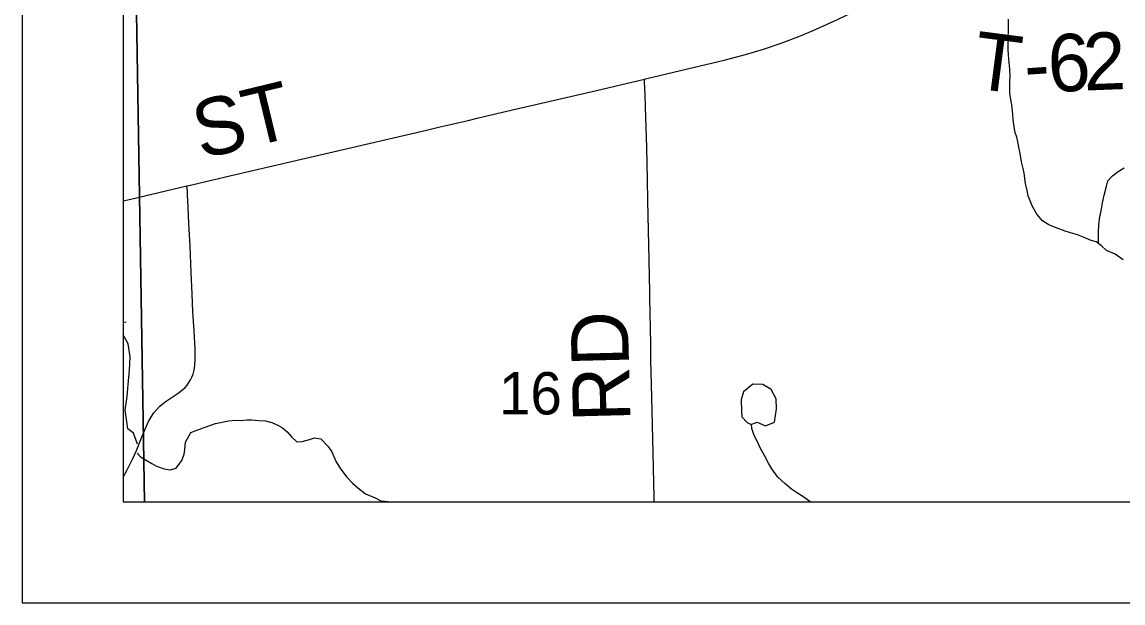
# Model space of a CAD drawing. Extents: x 0 to 34, y -5 to 22.
# Drawn here: x 2 to 3.09, y 14 to 14.575 of the extents above; entities that cross this region are included whole.
import ezdxf

# ---------------------------------------------------------------- set-up
doc = ezdxf.new("R2010")
doc.units = 0
for name, color, linetype in [('GM_X_City_Street', 7, 'Continuous'), ('GM_X_County_Road', 7, 'Continuous'), ('GM_X_County_Road_Text', 7, 'Continuous'), ('GM_X_Minor_Lake', 7, 'Continuous'), ('GM_X_Minor_River', 7, 'Continuous'), ('GM_X_Section_Text', 7, 'Continuous'), ('GM_X_Township_Road', 7, 'Continuous'), ('GM_X_Township_Road_Text', 7, 'Continuous'), ('GM_X_US_Route', 7, 'Continuous'), ('SH_Cut_Line', 7, 'Continuous'), ('SH_Data', 7, 'Continuous')]:
    doc.layers.add(name, color=color, linetype=linetype)

msp = doc.modelspace()

# ---------------------------------------------------------------- linework, layer by layer
at = {"layer": 'GM_X_City_Street'}
for points in [[(2.1212, 14.1), (3.1115, 14.1), (3.104, 14.6056), (2.1133, 14.5841)], [(2.1, 14.584), (2.1, 14.1), (2.1212, 14.1), (2.1133, 14.5841)]]:
    msp.add_lwpolyline(points, close=True, dxfattribs=at)
at = {"layer": 'GM_X_County_Road'}
msp.add_line((2.1, 14.2777), (2.103, 14.2784), dxfattribs=at)
for points in [[(2.6174, 14.5186), (2.6591, 14.5285), (2.6954, 14.5371), (2.7164, 14.5427), (2.7341, 14.5482), (2.7517, 14.5542), (2.7692, 14.5608), (2.7835, 14.5665), (2.8033, 14.5754), (2.82, 14.5835), (2.8336, 14.5909), (2.841, 14.5953)], [(2.1633, 14.4128), (2.168, 14.4139), (2.2072, 14.423), (2.2525, 14.4336), (2.2767, 14.4392), (2.3039, 14.4456), (2.4004, 14.4681), (2.4124, 14.4708), (2.4183, 14.4721), (2.4242, 14.4735), (2.433, 14.4755), (2.4419, 14.4776), (2.4508, 14.4797), (2.4659, 14.4833), (2.4901, 14.489), (2.5143, 14.4947), (2.5688, 14.5073), (2.6108, 14.517), (2.6164, 14.5184), (2.6174, 14.5186)], [(2.1, 14.3979), (2.1076, 14.3997), (2.1633, 14.4128)]]:
    msp.add_lwpolyline(points, dxfattribs=at)
at = {"layer": 'GM_X_Minor_Lake'}
for points in [[(2.1022, 14.1908), (2.104, 14.2045), (2.1051, 14.2163), (2.1065, 14.2304), (2.1072, 14.2437), (2.1052, 14.2566), (2.1, 14.2655)], [(2.7252, 14.1779), (2.7278, 14.179), (2.7361, 14.1752), (2.7452, 14.1791), (2.747, 14.192), (2.7466, 14.2019), (2.7419, 14.2114), (2.7336, 14.2162), (2.7237, 14.2165), (2.7143, 14.2089), (2.7121, 14.2009), (2.7125, 14.1899), (2.7129, 14.1842), (2.7179, 14.1785)], [(2.1143, 14.1571), (2.1105, 14.1681), (2.1048, 14.1725), (2.1022, 14.1908)], [(2.7179, 14.1785), (2.7208, 14.1773), (2.7228, 14.1771), (2.7252, 14.1779)]]:
    msp.add_lwpolyline(points, dxfattribs=at)
at = {"layer": 'GM_X_Minor_River'}
for points in [[(3.0905, 14.3397), (3.0824, 14.3453), (3.074, 14.3489), (3.0689, 14.3534), (3.0635, 14.3575), (3.0586, 14.3589), (3.0516, 14.3618), (3.0451, 14.3643), (3.0382, 14.3665), (3.0329, 14.3679), (3.0241, 14.3712), (3.0168, 14.3741), (3.0106, 14.3781), (3.0048, 14.3849), (3.0004, 14.3932), (2.9964, 14.403), (2.9952, 14.4083), (2.9935, 14.4151), (2.9922, 14.4254), (2.9913, 14.4299), (2.9897, 14.4367), (2.9884, 14.4447), (2.9875, 14.4496), (2.9859, 14.4564), (2.985, 14.461), (2.9834, 14.4655), (2.9825, 14.4712), (2.9816, 14.4784), (2.9811, 14.4838), (2.9802, 14.4929), (2.979, 14.4982), (2.9781, 14.5042), (2.978, 14.51), (2.9782, 14.516), (2.9785, 14.5218), (2.978, 14.5282), (2.9771, 14.5381), (2.9765, 14.5476), (2.9766, 14.5598), (2.9769, 14.5663), (2.9767, 14.5777)], [(3.0672, 14.3547), (3.0658, 14.356), (3.0658, 14.3606), (3.066, 14.3663), (3.0662, 14.3746), (3.0672, 14.3823), (3.0686, 14.388), (3.07, 14.396), (3.0714, 14.4037), (3.0739, 14.4125), (3.0753, 14.4178), (3.0798, 14.4229), (3.0854, 14.4272), (3.0914, 14.4307)], [(2.1141, 14.1483), (2.1156, 14.1464), (2.1172, 14.1445), (2.1284, 14.1379), (2.133, 14.1353), (2.1406, 14.1328), (2.1468, 14.1317), (2.1528, 14.1334), (2.1584, 14.1411), (2.1605, 14.1472), (2.1612, 14.1518), (2.1618, 14.159), (2.167, 14.1687), (2.1742, 14.1715), (2.1813, 14.1739), (2.1915, 14.1775), (2.2044, 14.1804), (2.2113, 14.1809), (2.217, 14.1807), (2.2227, 14.1811), (2.2273, 14.1812), (2.2345, 14.1806), (2.241, 14.1804), (2.2475, 14.1786), (2.2532, 14.176), (2.2579, 14.1734), (2.2625, 14.1693), (2.2668, 14.1645), (2.2722, 14.1596), (2.2775, 14.1597), (2.2847, 14.1618), (2.2896, 14.1634), (2.2958, 14.1624), (2.3027, 14.1553), (2.3067, 14.1496), (2.3086, 14.1451), (2.311, 14.1398), (2.3154, 14.1327), (2.3216, 14.1244), (2.3274, 14.1185), (2.3325, 14.114), (2.3402, 14.108), (2.3498, 14.104), (2.3552, 14.1011), (2.3624, 14.1005), (2.3678, 14.1002), (2.3723, 14.1003), (2.3749, 14.1)], [(2.7805, 14.1), (2.7804, 14.1001), (2.775, 14.1042), (2.768, 14.1086), (2.7619, 14.1127), (2.7553, 14.1183), (2.7483, 14.1246), (2.7424, 14.1329), (2.7393, 14.1385), (2.7353, 14.1461), (2.7314, 14.1528), (2.7278, 14.16), (2.725, 14.1657), (2.7226, 14.1728), (2.7222, 14.1772)]]:
    msp.add_lwpolyline(points, dxfattribs=at)
at = {"layer": 'GM_X_Township_Road'}
for points in [[(2.626, 14.1), (2.6259, 14.1047), (2.625, 14.1479), (2.6238, 14.2037), (2.6228, 14.2404), (2.6225, 14.2528), (2.6225, 14.259), (2.6224, 14.2686), (2.6222, 14.275), (2.6221, 14.2835), (2.6219, 14.2895), (2.6218, 14.2995), (2.6216, 14.3077), (2.6214, 14.3232), (2.6207, 14.3543), (2.6196, 14.3978), (2.6193, 14.4196), (2.6188, 14.4507), (2.6173, 14.4908), (2.6169, 14.5031), (2.6165, 14.5154), (2.6164, 14.5184)], [(2.1, 14.1246), (2.1037, 14.131), (2.1095, 14.1423), (2.1132, 14.1509), (2.1175, 14.1619), (2.1216, 14.1714), (2.1253, 14.1796), (2.1275, 14.1836), (2.1306, 14.1881), (2.133, 14.1911), (2.1365, 14.1949), (2.1416, 14.1991), (2.1496, 14.2045), (2.1546, 14.2075), (2.1593, 14.2113), (2.1615, 14.2134), (2.1635, 14.2156), (2.1652, 14.2182), (2.1667, 14.2208), (2.1682, 14.2234), (2.1694, 14.2265), (2.1705, 14.2303), (2.1711, 14.2351), (2.1715, 14.2412), (2.1713, 14.2509), (2.1704, 14.2694), (2.1693, 14.288), (2.1686, 14.306), (2.1674, 14.3271), (2.1664, 14.3536), (2.1653, 14.3756), (2.1646, 14.3919), (2.1639, 14.4041), (2.1637, 14.4072), (2.1633, 14.4128)]]:
    msp.add_lwpolyline(points, dxfattribs=at)
at = {"layer": 'GM_X_US_Route'}
msp.add_lwpolyline([(2.1, 16.5221), (2.1, 14.1), (6.156, 14.1)], dxfattribs=at)
at = {"layer": 'SH_Cut_Line'}
msp.add_lwpolyline([(2.1, 16.5221), (2.1, 14.1), (6.156, 14.1)], dxfattribs=at)
at = {"layer": 'SH_Data'}
for p, q in [((2, 21), (2, 14)), ((2.1, 20.9), (2.1, 14.1)), ((2.1, 14.1), (8.9, 14.1)), ((2.1, 14.1), (2.1, 14.1)), ((2, 14), (9, 14))]:
    msp.add_line(p, q, dxfattribs=at)

# ---------------------------------------------------------------- texts
at = {"layer": 'GM_X_County_Road_Text'}
msp.add_text('ST', height=0.05682, rotation=13.5997, dxfattribs=at).set_placement((2.1772, 14.4391))
at = {"layer": 'GM_X_Section_Text'}
msp.add_text('16', height=0.04186, rotation=0, dxfattribs=at).set_placement((2.4723, 14.1866))
at = {"layer": 'GM_X_Township_Road_Text'}
for s, height, rotation, p in [('T', 0.0568, 352.6039, (2.9397, 14.5098)), ('2', 0.0568, 2.2174, (3.0517, 14.5071)), ('6', 0.0568, 2.556, (3.0169, 14.5055)), ('-', 0.0568, 3.8064, (2.9939, 14.504)), ('RD', 0.05682, 91.4514, (2.6025, 14.1798))]:
    msp.add_text(s, height=height, rotation=rotation, dxfattribs=at).set_placement(p)

doc.saveas('drawing.dxf')
